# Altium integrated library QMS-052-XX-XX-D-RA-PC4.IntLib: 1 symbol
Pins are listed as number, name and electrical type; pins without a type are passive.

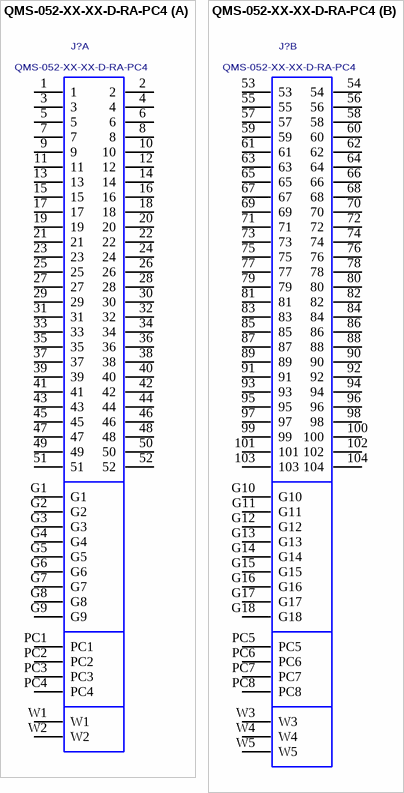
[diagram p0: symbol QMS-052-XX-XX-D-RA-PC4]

## QMS-052-XX-XX-D-RA-PC4
designator J?
0.635MM DUAL ROW RIGHT ANGLE PLUG ASSEMBLY; MANUFACTURER: SAMTEC
footprint QMS-052-XX-XX-D-RA-PC4
part A pins: 1, 2, 3, 4, 5, 6, 7, 8, 9, 10, 11, 12, 13, 14, 15, 16, 17, 18, 19, 20, 21, 22, 23, 24, 25, 26, 27, 28, 29, 30, 31, 32, 33, 34, 35, 36, 37, 38, 39, 40, 41, 42, 43, 44, 45, 46, 47, 48, 49, 50, 51, 52, G1, G2, G3, G4, G5, G6, G7, G8, G9, PC1, PC2, PC3, PC4, W1, W2
part B pins: 53, 54, 55, 56, 57, 58, 59, 60, 61, 62, 63, 64, 65, 66, 67, 68, 69, 70, 71, 72, 73, 74, 75, 76, 77, 78, 79, 80, 81, 82, 83, 84, 85, 86, 87, 88, 89, 90, 91, 92, 93, 94, 95, 96, 97, 98, 99, 100, 101, 102, 103, 104, G10, G11, G12, G13, G14, G15, G16, G17, G18, PC5, PC6, PC7, PC8, W3, W4, W5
